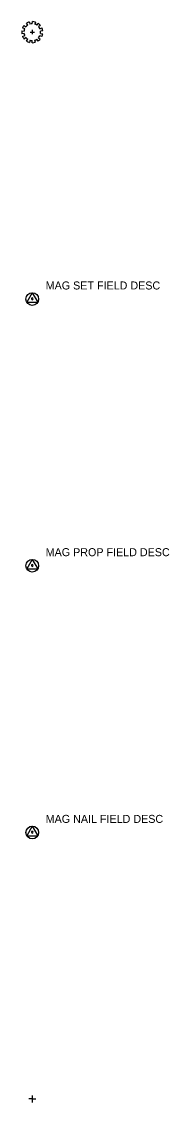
# Model space of a CAD drawing. Extents: x 98 to 2902, y -6 to 903.
# Drawn here: x 1298 to 1325.6, y -0.6 to 202 of the extents above; entities that cross this region are included whole.
import ezdxf

# ---------------------------------------------------------------- set-up
doc = ezdxf.new("R2010")
doc.units = 0
for name, color, linetype in [('V-SITE-OTLN', 7, 'Continuous'), ('V-SITE-VEGE', 7, 'Continuous'), ('V-SURV-DATA', 7, 'Continuous')]:
    doc.layers.add(name, color=color, linetype=linetype)

msp = doc.modelspace()

# ---------------------------------------------------------------- linework, layer by layer
at = {"layer": 'V-SITE-OTLN'}
for p, q in [((1300, 0.65), (1300, -0.65)), ((1300, 0), (1299.35, 0)), ((1300, 0), (1300.65, 0))]:
    msp.add_line(p, q, dxfattribs=at)
at = {"layer": 'V-SITE-VEGE'}
for p, q in [((1298.58, 200.61), (1298.19, 200.78)), ((1298.49, 201.26), (1298.81, 200.98)), ((1299.17, 201.3), (1298.93, 201.65)), ((1299.46, 201.89), (1299.56, 201.47)), ((1300, 201.53), (1300.01, 201.96)), ((1300.57, 201.88), (1300.45, 201.47)), ((1300.84, 201.29), (1301.08, 201.64)), ((1301.51, 201.27), (1301.19, 200.99)), ((1301.42, 200.62), (1301.8, 200.82)), ((1298.03, 200.25), (1298.46, 200.18)), ((1298.46, 199.76), (1298.04, 199.69)), ((1298.19, 199.16), (1298.58, 199.35)), ((1298.83, 198.96), (1298.5, 198.68)), ((1298.94, 198.3), (1299.15, 198.68)), ((1299.58, 200), (1300.42, 200)), ((1300, 200.42), (1300, 199.58)), ((1301.08, 198.31), (1300.85, 198.68)), ((1301.17, 198.95), (1301.5, 198.68)), ((1301.81, 199.15), (1301.41, 199.31)), ((1301.97, 200.25), (1301.54, 200.19)), ((1301.54, 199.75), (1301.97, 199.7)), ((1299.58, 198.48), (1299.46, 198.07)), ((1300, 197.99), (1300, 198.42)), ((1300.43, 198.49), (1300.56, 198.08))]:
    msp.add_line(p, q, dxfattribs=at)
for radius, start, end in [(1.98, 139.7777, 156.0738), (1.56, 156.0557, 172.7558), (1.56, 122.254, 140.086), (1.98, 105.972, 122.5562), (1.56, 89.9461, 106.3473), (1.98, 73.2952, 89.5718), (1.56, 57.451, 73.0843), (1.98, 40.7122, 57.1166), (1.56, 24.4529, 40.4774), (1.98, 7.9671, 24.8625), (1.98, 172.27, 188.583), (1.98, 204.5394, 220.9852), (1.56, 188.0619, 204.0332), (1.56, 221.2062, 236.7795), (1.56, 285.9559, 303.0564), (1.98, 302.8434, 319.0222), (1.56, 318.6432, 334.5795), (1.56, 351.5431, 7.6203), (1.98, 335.3123, 351.7042), (1.98, 237.6108, 254.1981), (1.56, 254.31, 270.043), (1.98, 270.0356, 286.342)]:
    msp.add_arc((1300, 199.98), radius, start, end, dxfattribs=at)
at = {"layer": 'V-SURV-DATA'}
for p, q in [((1300, 151.14), (1298.97, 149.35)), ((1300, 151.14), (1301.03, 149.35)), ((1298.97, 149.35), (1301.03, 149.35)), ((1300, 101.14), (1298.97, 99.35)), ((1298.97, 99.35), (1301.03, 99.35)), ((1300, 101.14), (1301.03, 99.35)), ((1300, 51.14), (1298.97, 49.35)), ((1300, 51.14), (1301.03, 49.35)), ((1298.97, 49.35), (1301.03, 49.35))]:
    msp.add_line(p, q, dxfattribs=at)
for centre in [(1300, 149.95), (1300, 99.95), (1300, 49.95)]:
    msp.add_circle(centre, 1.19, dxfattribs=at)
for centre in [(1300, 150), (1300, 100), (1300, 50)]:
    msp.add_arc(centre, 0.165, 92.2877, 90.5674, dxfattribs=at)

# ---------------------------------------------------------------- texts
for s, p in [('MAG SET FIELD DESC', (1302.5, 151.75)), ('MAG PROP FIELD DESC', (1302.5, 101.75)), ('MAG NAIL FIELD DESC', (1302.5, 51.75))]:
    msp.add_text(s, height=1.5, dxfattribs=at).set_placement(p)

doc.saveas('drawing.dxf')
